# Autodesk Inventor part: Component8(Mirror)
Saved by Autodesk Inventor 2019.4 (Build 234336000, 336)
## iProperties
Created: 2020-06
Part Number: Component8(Mirror)
Material: Generic
Document SubType Name: Modeling
Designer: Administrator
Density: 1 g/cm^3
Appearance: Default
Title: Component8(Mirror)
Author: Administrator
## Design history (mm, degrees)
